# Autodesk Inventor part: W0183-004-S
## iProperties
Shininess: 64.0
Length Units: 11272
Angle Units: 11279
Time Units: 11290
Mass Units: 11286
Length Display Precision: 3
Angle Display Precision: 2
Compacted: True
Part Number: W0183-004-S
Document SubType Name: Modeling
Created: 2005-07
Designer: Administrator
Manufacturer: Standard
Standards Organization: Custom
Material: Stainless Steel, Austenitic
Description: WAVE WSHR W0183-004-S
Density: 0.0
Volumn: 0.0
Area: 0.0
PropertySet Name: Model Information
Control State: 0
Master: False
Checked Out: False
Author: Administrator
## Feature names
1. Extrusion1
2. Extrusion2
3. Loft1
4. Fillet1
5. Mirror1
6. Circular Pattern1
7. Extrusion3
